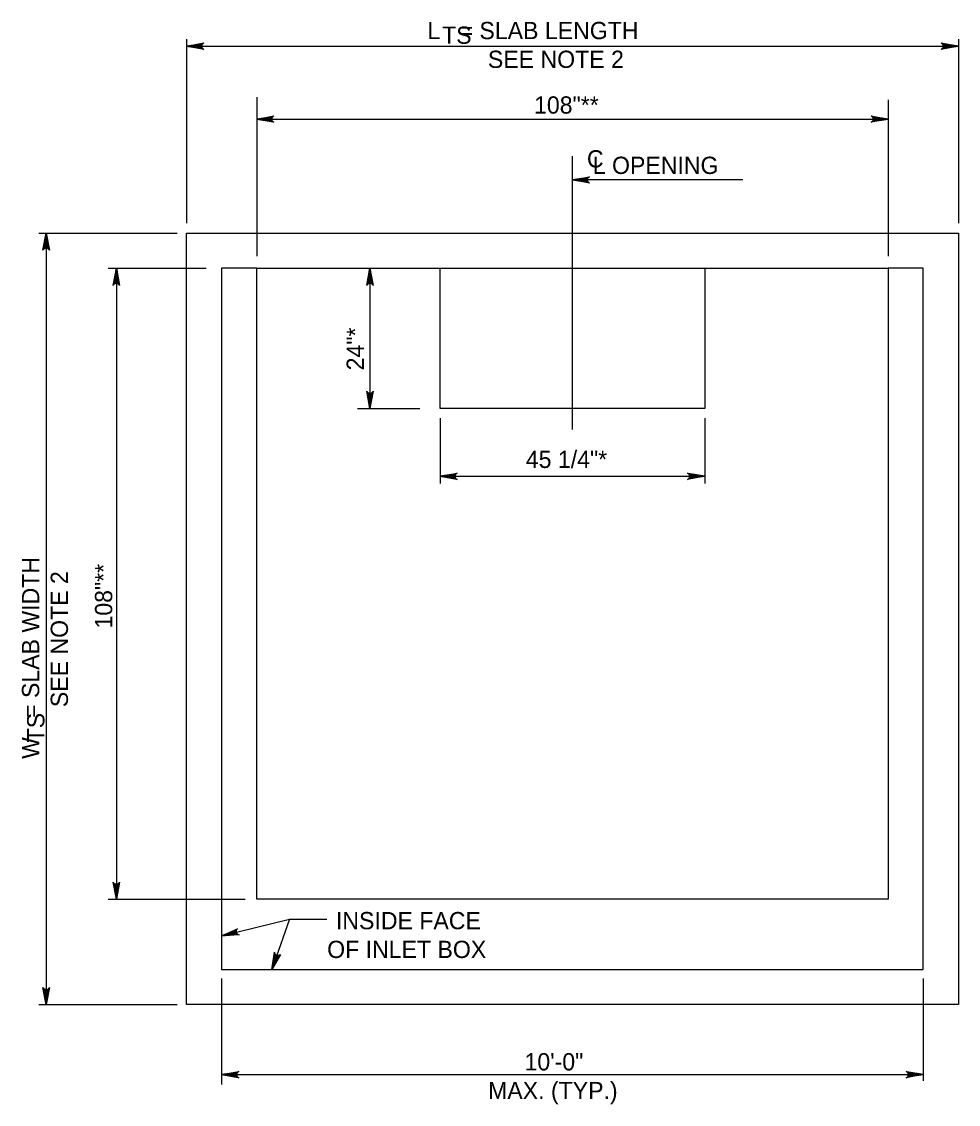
# Model space of a CAD drawing. Extents: x -6420 to 49575, y -4552 to 11624.
# Drawn here: x 6092 to 6626, y 8441 to 9058 of the extents above; entities that cross this region are included whole.
import ezdxf

# ---------------------------------------------------------------- set-up
doc = ezdxf.new("R2010")
doc.units = 0
doc.layers.add('1', color=7, linetype='Continuous')

msp = doc.modelspace()

# ---------------------------------------------------------------- linework, layer by layer
at = {"layer": '1'}
for p, q in [((6185.66, 9048.22), (6185.66, 8943.3)), ((6625.66, 9048.22), (6625.66, 8943.3)), ((6185.66, 9044.23), (6625.66, 9044.23)), ((6225.66, 9015.07), (6225.66, 8924.46)), ((6585.66, 9013.54), (6585.66, 8924.46)), ((6225.66, 9002.63), (6585.66, 9002.63)), ((6405.66, 8825.61), (6405.66, 8981.42)), ((6502.75, 8967.96), (6405.66, 8967.96)), ((6101.41, 8937.57), (6180.4, 8937.57)), ((6105.66, 8937.57), (6105.66, 8497.57)), ((6141.04, 8917.57), (6196.9, 8917.57)), ((6145.66, 8917.57), (6145.66, 8557.57)), ((6225.66, 8917.57), (6205.66, 8917.57)), ((6205.66, 8917.57), (6205.66, 8517.57)), ((6290.24, 8917.57), (6290.24, 8837.57)), ((6330.24, 8917.57), (6481.07, 8917.57)), ((6330.24, 8837.57), (6330.24, 8917.57)), ((6481.07, 8917.57), (6481.07, 8837.57)), ((6605.66, 8917.57), (6585.66, 8917.57)), ((6605.66, 8517.57), (6605.66, 8917.57)), ((6283.2, 8837.57), (6318.72, 8837.57)), ((6481.07, 8837.57), (6330.24, 8837.57)), ((6330.24, 8831.98), (6330.24, 8794.68)), ((6481.07, 8831.98), (6481.07, 8794.68)), ((6330.24, 8798.89), (6481.07, 8798.89)), ((6141.04, 8557.57), (6219.05, 8557.57)), ((6205.66, 8536.68), (6244.34, 8546.29)), ((6244.34, 8546.29), (6234.21, 8517.57)), ((6244.34, 8546.29), (6265.55, 8546.29)), ((6205.66, 8517.57), (6605.66, 8517.57)), ((6205.66, 8512.44), (6205.66, 8452.02)), ((6605.66, 8512.44), (6605.66, 8453.96)), ((6101.41, 8497.57), (6180.4, 8497.57)), ((6205.66, 8457.57), (6605.66, 8457.57))]:
    msp.add_line(p, q, dxfattribs=at)
for points in [[(6185.66, 9044.23), (6195.44, 9046.07), (6195.07, 9045.81), (6194.69, 9045.55), (6194.49, 9045.22), (6194.3, 9044.89), (6194.24, 9044.56), (6194.19, 9044.23), (6194.24, 9043.91), (6194.3, 9043.58), (6194.49, 9043.25), (6194.69, 9042.92), (6195.07, 9042.66), (6195.44, 9042.4), (6185.66, 9044.23), (6195.07, 9042.66), (6194.69, 9042.92), (6185.66, 9044.23), (6194.49, 9043.25), (6194.3, 9043.58), (6185.66, 9044.23), (6194.24, 9043.91), (6194.19, 9044.23), (6185.66, 9044.23), (6194.24, 9044.56), (6194.3, 9044.89), (6185.66, 9044.23), (6194.49, 9045.22), (6194.69, 9045.55), (6185.66, 9044.23), (6195.07, 9045.81)], [(6625.66, 9044.23), (6615.87, 9042.4), (6616.25, 9042.66), (6616.63, 9042.92), (6616.82, 9043.25), (6617.01, 9043.58), (6617.07, 9043.91), (6617.13, 9044.23), (6617.07, 9044.56), (6617.01, 9044.89), (6616.82, 9045.22), (6616.63, 9045.55), (6616.25, 9045.81), (6615.87, 9046.07), (6625.66, 9044.23), (6616.25, 9045.81), (6616.63, 9045.55), (6625.66, 9044.23), (6616.82, 9045.22), (6617.01, 9044.89), (6625.66, 9044.23), (6617.07, 9044.56), (6617.13, 9044.23), (6625.66, 9044.23), (6617.07, 9043.91), (6617.01, 9043.58), (6625.66, 9044.23), (6616.82, 9043.25), (6616.63, 9042.92), (6625.66, 9044.23), (6616.25, 9042.66)], [(6225.66, 9002.63), (6235.44, 9004.46), (6235.07, 9004.2), (6234.69, 9003.94), (6234.49, 9003.61), (6234.3, 9003.28), (6234.24, 9002.95), (6234.19, 9002.63), (6234.24, 9002.3), (6234.3, 9001.97), (6234.49, 9001.64), (6234.69, 9001.31), (6235.07, 9001.05), (6235.44, 9000.79), (6225.66, 9002.63), (6235.07, 9001.05), (6234.69, 9001.31), (6225.66, 9002.63), (6234.49, 9001.64), (6234.3, 9001.97), (6225.66, 9002.63), (6234.24, 9002.3), (6234.19, 9002.63), (6225.66, 9002.63), (6234.24, 9002.95), (6234.3, 9003.28), (6225.66, 9002.63), (6234.49, 9003.61), (6234.69, 9003.94), (6225.66, 9002.63), (6235.07, 9004.2)], [(6585.66, 9002.63), (6575.87, 9000.79), (6576.25, 9001.05), (6576.63, 9001.31), (6576.82, 9001.64), (6577.01, 9001.97), (6577.07, 9002.3), (6577.13, 9002.63), (6577.07, 9002.95), (6577.01, 9003.28), (6576.82, 9003.61), (6576.63, 9003.94), (6576.25, 9004.2), (6575.87, 9004.46), (6585.66, 9002.63), (6576.25, 9004.2), (6576.63, 9003.94), (6585.66, 9002.63), (6576.82, 9003.61), (6577.01, 9003.28), (6585.66, 9002.63), (6577.07, 9002.95), (6577.13, 9002.63), (6585.66, 9002.63), (6577.07, 9002.3), (6577.01, 9001.97), (6585.66, 9002.63), (6576.82, 9001.64), (6576.63, 9001.31), (6585.66, 9002.63), (6576.25, 9001.05)], [(6405.66, 8967.96), (6415.44, 8969.79), (6415.07, 8969.53), (6414.69, 8969.27), (6414.49, 8968.94), (6414.3, 8968.61), (6414.24, 8968.29), (6414.19, 8967.96), (6414.24, 8967.63), (6414.3, 8967.3), (6414.49, 8966.97), (6414.69, 8966.65), (6415.07, 8966.38), (6415.44, 8966.12), (6405.66, 8967.96), (6415.07, 8966.38), (6414.69, 8966.65), (6405.66, 8967.96), (6414.49, 8966.97), (6414.3, 8967.3), (6405.66, 8967.96), (6414.24, 8967.63), (6414.19, 8967.96), (6405.66, 8967.96), (6414.24, 8968.29), (6414.3, 8968.61), (6405.66, 8967.96), (6414.49, 8968.94), (6414.69, 8969.27), (6405.66, 8967.96), (6415.07, 8969.53)], [(6105.66, 8937.57), (6107.49, 8927.78), (6107.23, 8928.16), (6106.97, 8928.53), (6106.64, 8928.73), (6106.31, 8928.92), (6105.98, 8928.98), (6105.66, 8929.04), (6105.33, 8928.98), (6105, 8928.92), (6104.67, 8928.73), (6104.34, 8928.53), (6104.08, 8928.16), (6103.82, 8927.78), (6105.66, 8937.57), (6104.08, 8928.16), (6104.34, 8928.53), (6105.66, 8937.57), (6104.67, 8928.73), (6105, 8928.92), (6105.66, 8937.57), (6105.33, 8928.98), (6105.66, 8929.04), (6105.66, 8937.57), (6105.98, 8928.98), (6106.31, 8928.92), (6105.66, 8937.57), (6106.64, 8928.73), (6106.97, 8928.53), (6105.66, 8937.57), (6107.23, 8928.16)], [(6145.66, 8917.57), (6147.49, 8907.78), (6147.23, 8908.16), (6146.97, 8908.53), (6146.64, 8908.73), (6146.31, 8908.92), (6145.98, 8908.98), (6145.66, 8909.04), (6145.33, 8908.98), (6145, 8908.92), (6144.67, 8908.73), (6144.34, 8908.53), (6144.08, 8908.16), (6143.82, 8907.78), (6145.66, 8917.57), (6144.08, 8908.16), (6144.34, 8908.53), (6145.66, 8917.57), (6144.67, 8908.73), (6145, 8908.92), (6145.66, 8917.57), (6145.33, 8908.98), (6145.66, 8909.04), (6145.66, 8917.57), (6145.98, 8908.98), (6146.31, 8908.92), (6145.66, 8917.57), (6146.64, 8908.73), (6146.97, 8908.53), (6145.66, 8917.57), (6147.23, 8908.16)], [(6481.07, 8917.57), (6585.66, 8917.57), (6585.66, 8557.57), (6225.66, 8557.57), (6225.66, 8917.57), (6330.24, 8917.57)], [(6290.24, 8917.57), (6292.08, 8907.78), (6291.81, 8908.16), (6291.55, 8908.53), (6291.22, 8908.73), (6290.9, 8908.92), (6290.57, 8908.98), (6290.24, 8909.04), (6289.91, 8908.98), (6289.58, 8908.92), (6289.26, 8908.73), (6288.93, 8908.53), (6288.67, 8908.16), (6288.41, 8907.78), (6290.24, 8917.57), (6288.67, 8908.16), (6288.93, 8908.53), (6290.24, 8917.57), (6289.26, 8908.73), (6289.58, 8908.92), (6290.24, 8917.57), (6289.91, 8908.98), (6290.24, 8909.04), (6290.24, 8917.57), (6290.57, 8908.98), (6290.9, 8908.92), (6290.24, 8917.57), (6291.22, 8908.73), (6291.55, 8908.53), (6290.24, 8917.57), (6291.81, 8908.16)], [(6290.24, 8837.57), (6288.41, 8847.35), (6288.67, 8846.97), (6288.93, 8846.6), (6289.26, 8846.4), (6289.58, 8846.21), (6289.91, 8846.15), (6290.24, 8846.1), (6290.57, 8846.15), (6290.9, 8846.21), (6291.22, 8846.4), (6291.55, 8846.6), (6291.81, 8846.97), (6292.08, 8847.35), (6290.24, 8837.57), (6291.81, 8846.97), (6291.55, 8846.6), (6290.24, 8837.57), (6291.22, 8846.4), (6290.9, 8846.21), (6290.24, 8837.57), (6290.57, 8846.15), (6290.24, 8846.1), (6290.24, 8837.57), (6289.91, 8846.15), (6289.58, 8846.21), (6290.24, 8837.57), (6289.26, 8846.4), (6288.93, 8846.6), (6290.24, 8837.57), (6288.67, 8846.97)], [(6330.24, 8798.89), (6340.03, 8800.72), (6339.65, 8800.46), (6339.27, 8800.2), (6339.08, 8799.87), (6338.88, 8799.55), (6338.83, 8799.22), (6338.77, 8798.89), (6338.83, 8798.56), (6338.88, 8798.23), (6339.08, 8797.9), (6339.27, 8797.58), (6339.65, 8797.32), (6340.03, 8797.05), (6330.24, 8798.89), (6339.65, 8797.32), (6339.27, 8797.58), (6330.24, 8798.89), (6339.08, 8797.9), (6338.88, 8798.23), (6330.24, 8798.89), (6338.83, 8798.56), (6338.77, 8798.89), (6330.24, 8798.89), (6338.83, 8799.22), (6338.88, 8799.55), (6330.24, 8798.89), (6339.08, 8799.87), (6339.27, 8800.2), (6330.24, 8798.89), (6339.65, 8800.46)], [(6481.07, 8798.89), (6471.29, 8797.05), (6471.66, 8797.32), (6472.04, 8797.58), (6472.24, 8797.9), (6472.43, 8798.23), (6472.49, 8798.56), (6472.54, 8798.89), (6472.49, 8799.22), (6472.43, 8799.55), (6472.24, 8799.87), (6472.04, 8800.2), (6471.66, 8800.46), (6471.29, 8800.72), (6481.07, 8798.89), (6471.66, 8800.46), (6472.04, 8800.2), (6481.07, 8798.89), (6472.24, 8799.87), (6472.43, 8799.55), (6481.07, 8798.89), (6472.49, 8799.22), (6472.54, 8798.89), (6481.07, 8798.89), (6472.49, 8798.56), (6472.43, 8798.23), (6481.07, 8798.89), (6472.24, 8797.9), (6472.04, 8797.58), (6481.07, 8798.89), (6471.66, 8797.32)], [(6145.66, 8557.57), (6143.82, 8567.35), (6144.08, 8566.97), (6144.34, 8566.6), (6144.67, 8566.4), (6145, 8566.21), (6145.33, 8566.15), (6145.66, 8566.1), (6145.98, 8566.15), (6146.31, 8566.21), (6146.64, 8566.4), (6146.97, 8566.6), (6147.23, 8566.97), (6147.49, 8567.35), (6145.66, 8557.57), (6147.23, 8566.97), (6146.97, 8566.6), (6145.66, 8557.57), (6146.64, 8566.4), (6146.31, 8566.21), (6145.66, 8557.57), (6145.98, 8566.15), (6145.66, 8566.1), (6145.66, 8557.57), (6145.33, 8566.15), (6145, 8566.21), (6145.66, 8557.57), (6144.67, 8566.4), (6144.34, 8566.6), (6145.66, 8557.57), (6144.08, 8566.97)], [(6205.66, 8536.68), (6214.71, 8540.82), (6214.41, 8540.48), (6214.1, 8540.13), (6214, 8539.77), (6213.89, 8539.4), (6213.91, 8539.07), (6213.93, 8538.74), (6214.07, 8538.43), (6214.2, 8538.13), (6214.47, 8537.86), (6214.74, 8537.59), (6215.17, 8537.42), (6215.6, 8537.26), (6205.66, 8536.68), (6215.17, 8537.42), (6214.74, 8537.59), (6205.66, 8536.68), (6214.47, 8537.86), (6214.2, 8538.13), (6205.66, 8536.68), (6214.07, 8538.43), (6213.93, 8538.74), (6205.66, 8536.68), (6213.91, 8539.07), (6213.89, 8539.4), (6205.66, 8536.68), (6214, 8539.77), (6214.1, 8540.13), (6205.66, 8536.68), (6214.41, 8540.48)], [(6234.21, 8517.57), (6235.73, 8527.41), (6235.85, 8526.96), (6235.97, 8526.52), (6236.22, 8526.23), (6236.46, 8525.94), (6236.75, 8525.77), (6237.05, 8525.61), (6237.37, 8525.56), (6237.7, 8525.5), (6238.08, 8525.57), (6238.45, 8525.65), (6238.82, 8525.92), (6239.19, 8526.19), (6234.21, 8517.57), (6238.82, 8525.92), (6238.45, 8525.65), (6234.21, 8517.57), (6238.08, 8525.57), (6237.7, 8525.5), (6234.21, 8517.57), (6237.37, 8525.56), (6237.05, 8525.61), (6234.21, 8517.57), (6236.75, 8525.77), (6236.46, 8525.94), (6234.21, 8517.57), (6236.22, 8526.23), (6235.97, 8526.52), (6234.21, 8517.57), (6235.85, 8526.96)], [(6105.66, 8497.57), (6103.82, 8507.35), (6104.08, 8506.97), (6104.34, 8506.6), (6104.67, 8506.4), (6105, 8506.21), (6105.33, 8506.15), (6105.66, 8506.1), (6105.98, 8506.15), (6106.31, 8506.21), (6106.64, 8506.4), (6106.97, 8506.6), (6107.23, 8506.97), (6107.49, 8507.35), (6105.66, 8497.57), (6107.23, 8506.97), (6106.97, 8506.6), (6105.66, 8497.57), (6106.64, 8506.4), (6106.31, 8506.21), (6105.66, 8497.57), (6105.98, 8506.15), (6105.66, 8506.1), (6105.66, 8497.57), (6105.33, 8506.15), (6105, 8506.21), (6105.66, 8497.57), (6104.67, 8506.4), (6104.34, 8506.6), (6105.66, 8497.57), (6104.08, 8506.97)], [(6205.66, 8457.57), (6215.44, 8459.4), (6215.07, 8459.14), (6214.69, 8458.88), (6214.49, 8458.55), (6214.3, 8458.22), (6214.24, 8457.89), (6214.19, 8457.57), (6214.24, 8457.24), (6214.3, 8456.91), (6214.49, 8456.58), (6214.69, 8456.25), (6215.07, 8455.99), (6215.44, 8455.73), (6205.66, 8457.57), (6215.07, 8455.99), (6214.69, 8456.25), (6205.66, 8457.57), (6214.49, 8456.58), (6214.3, 8456.91), (6205.66, 8457.57), (6214.24, 8457.24), (6214.19, 8457.57), (6205.66, 8457.57), (6214.24, 8457.89), (6214.3, 8458.22), (6205.66, 8457.57), (6214.49, 8458.55), (6214.69, 8458.88), (6205.66, 8457.57), (6215.07, 8459.14)], [(6605.66, 8457.57), (6595.87, 8455.73), (6596.25, 8455.99), (6596.63, 8456.25), (6596.82, 8456.58), (6597.01, 8456.91), (6597.07, 8457.24), (6597.13, 8457.57), (6597.07, 8457.89), (6597.01, 8458.22), (6596.82, 8458.55), (6596.63, 8458.88), (6596.25, 8459.14), (6595.87, 8459.4), (6605.66, 8457.57), (6596.25, 8459.14), (6596.63, 8458.88), (6605.66, 8457.57), (6596.82, 8458.55), (6597.01, 8458.22), (6605.66, 8457.57), (6597.07, 8457.89), (6597.13, 8457.57), (6605.66, 8457.57), (6597.07, 8457.24), (6597.01, 8456.91), (6605.66, 8457.57), (6596.82, 8456.58), (6596.63, 8456.25), (6605.66, 8457.57), (6596.25, 8455.99)]]:
    msp.add_lwpolyline(points, dxfattribs=at)
msp.add_lwpolyline([(6185.66, 8937.57), (6625.66, 8937.57), (6625.66, 8497.57), (6185.66, 8497.57)], close=True, dxfattribs=at)

# ---------------------------------------------------------------- texts
for s, height, p in [('L   = SLAB LENGTH', 9.8425, (6323, 9048.23)), ('TS', 9.843, (6331.35, 9045.59)), ('SEE NOTE 2', 9.843, (6357.45, 9031.83)), ('108"**', 9.843, (6383.77, 9005.76)), ('C', 9.84, (6413.92, 8975.05)), ('L OPENING', 9.843, (6417.25, 8971.34)), ('45 1/4"*', 9.843, (6379.08, 8803.62)), ('INSIDE FACE', 9.8425, (6270.83, 8540.5)), ('OF INLET BOX', 9.8425, (6265.83, 8524.1)), ('10\'-0"', 9.843, (6378.34, 8459.99)), ('MAX. (TYP.)', 9.8425, (6357.57, 8443.58))]:
    msp.add_text(s, height=height, dxfattribs=at).set_placement(p)
for s, height, p in [('24"*', 9.843, (6286.74, 8859.32)), ('W   = SLAB WIDTH', 9.8425, (6101.66, 8637.67)), ('108"**', 9.843, (6143.3, 8712.05)), ('SEE NOTE 2', 9.843, (6118.06, 8667.2)), ('TS', 9.843, (6104.63, 8647.1))]:
    msp.add_text(s, height=height, rotation=90, dxfattribs=at).set_placement(p)

doc.saveas('drawing.dxf')
